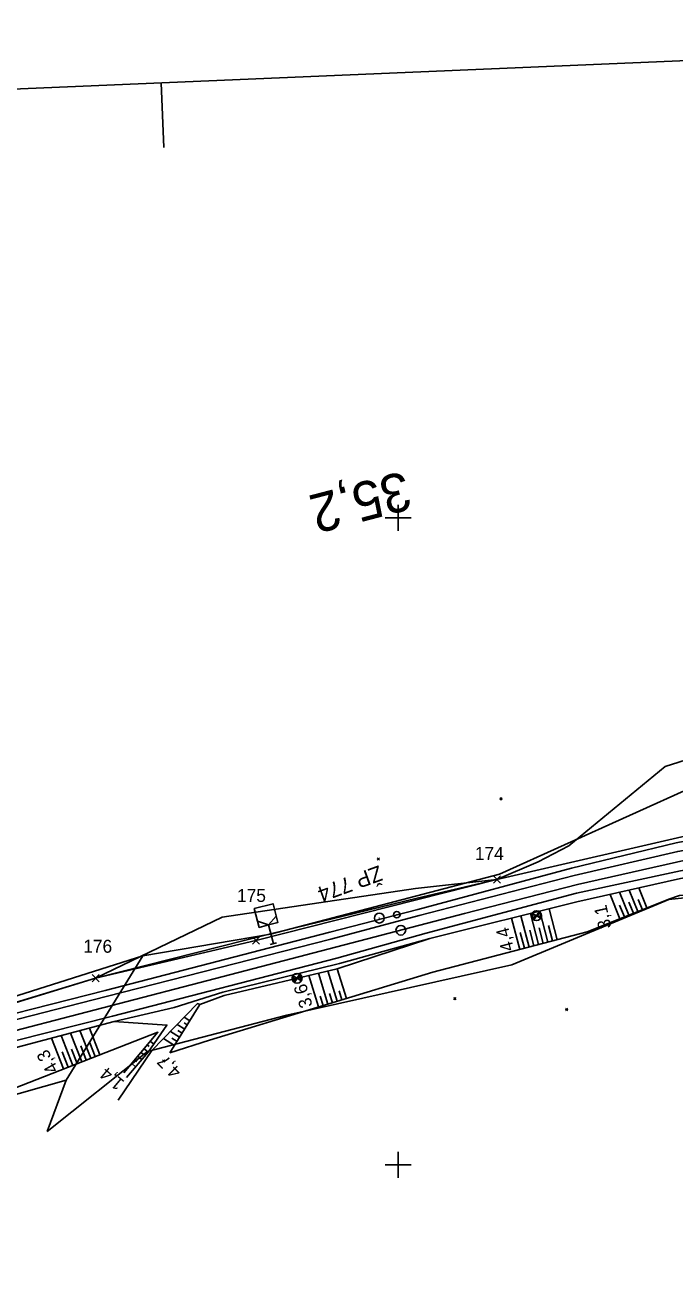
# Model space of a CAD drawing. Extents: x -806456 to -805395, y -1150847 to -1150506.
# Drawn here: x -806057.6 to -805957.2, y -1150719.3 to -1150523.9 of the extents above; entities that cross this region are included whole.
import ezdxf

# ---------------------------------------------------------------- set-up
doc = ezdxf.new("R2010")
doc.units = 0
for name, color, linetype in [('0381KM032-037P - Vrstva 1', 7, 'Continuous'), ('0381KM032-037P - Vrstva 4', 7, 'Continuous'), ('0381KM032-037P - Vrstva 48', 7, 'Continuous'), ('0381KM032-037P - Vrstva 49', 7, 'Continuous'), ('0381KM032-037P - Vrstva 55', 7, 'Continuous'), ('0381KM032-037P - Vrstva 7', 7, 'Continuous'), ('Default', 7, 'Continuous'), ('formát', 7, 'Continuous'), ('hran DP - hran DP', 7, 'Continuous'), ('krizky_1000 - Vrstva 1', 7, 'Continuous'), ('PSR_C2_2_Lomove_body_Vimperk - Vrstva 60', 7, 'Continuous'), ('PSR_C2_2_trasa_Vimperk - Kabelová trasa', 7, 'Continuous'), ('vyt_sit - stávající', 7, 'Continuous')]:
    doc.layers.add(name, color=color, linetype=linetype)

msp = doc.modelspace()

# ---------------------------------------------------------------- linework, layer by layer
at = {"layer": '0381KM032-037P - Vrstva 1'}
for points in [[(-805955.36, -1150652.84), (-805972.27, -1150656.66), (-805989.76, -1150661.17)], [(-805989.76, -1150661.17), (-806027.03, -1150670.9), (-806064.32, -1150680.56), (-806101.67, -1150690.24), (-806138.44, -1150699.75), (-806158.28, -1150704.94), (-806163.64, -1150706.34), (-806175.38, -1150709.4), (-806186.46, -1150712.29), (-806205.2, -1150717.19), (-806213.26, -1150719.29)]]:
    msp.add_lwpolyline(points, dxfattribs=at)
at = {"layer": '0381KM032-037P - Vrstva 4'}
for points in [[(-805920.59, -1150645.08), (-805938.49, -1150646.69), (-805957, -1150650.24), (-805973.18, -1150654.13), (-805996.94, -1150660.52), (-806010.57, -1150664.04), (-806045.29, -1150673.07), (-806070.44, -1150679.45), (-806076.44, -1150680.94), (-806080.95, -1150682.04), (-806094.16, -1150685.34), (-806107.83, -1150689.09)], [(-805923.83, -1150646.61), (-805939.39, -1150648.49), (-805956.78, -1150651.56), (-805972.77, -1150655.27), (-805996.74, -1150661.47), (-806010.38, -1150665.11), (-806045.15, -1150673.98), (-806070.28, -1150680.43), (-806094.02, -1150686.67), (-806107.78, -1150690.05)], [(-805923.37, -1150650.9), (-805938.15, -1150652.42), (-805956.35, -1150655.74), (-805972.37, -1150659.35), (-805995.12, -1150665.03), (-806009.04, -1150668.86), (-806027.1, -1150673.31), (-806034.62, -1150675.7), (-806043.91, -1150677.85), (-806068.97, -1150684.48)], [(-805923.42, -1150649.97), (-805938.4, -1150651.47), (-805956.35, -1150654.55), (-805972.44, -1150657.98), (-805995.68, -1150664.21)], [(-805995.68, -1150664.21), (-806009.49, -1150668.04), (-806044.17, -1150677), (-806069.3, -1150683.37)]]:
    msp.add_lwpolyline(points, dxfattribs=at)
at = {"layer": '0381KM032-037P - Vrstva 48'}
for p, q in [((-805962.94, -1150660.84), (-805964.27, -1150657.52)), ((-805961.55, -1150660.28), (-805962.79, -1150657.19)), ((-805965.72, -1150661.96), (-805967.24, -1150658.19)), ((-805964.33, -1150661.4), (-805965.76, -1150657.86)), ((-805963.64, -1150661.12), (-805964.33, -1150659.41)), ((-805962.24, -1150660.56), (-805962.89, -1150658.96)), ((-805978.31, -1150665.95), (-805979.56, -1150661.14)), ((-805976.86, -1150665.57), (-805978.1, -1150660.78)), ((-805975.4, -1150665.2), (-805976.65, -1150660.41)), ((-805965.03, -1150661.68), (-805965.76, -1150659.85)), ((-805981.21, -1150666.7), (-805982.47, -1150661.87)), ((-805979.76, -1150666.33), (-805981.01, -1150661.51)), ((-805977.58, -1150665.76), (-805978.21, -1150663.36)), ((-805976.13, -1150665.38), (-805976.75, -1150662.99)), ((-805980.48, -1150666.52), (-805981.11, -1150664.1)), ((-805979.03, -1150666.14), (-805979.66, -1150663.73)), ((-806012.31, -1150675.59), (-806013.79, -1150670.73)), ((-806010.87, -1150675.15), (-806012.33, -1150670.38)), ((-806009.44, -1150674.72), (-806010.87, -1150670.03)), ((-806008, -1150674.28), (-806009.41, -1150669.68)), ((-806008.72, -1150674.5), (-806009.14, -1150673.1)), ((-806011.59, -1150675.37), (-806012.03, -1150673.93)), ((-806010.15, -1150674.93), (-806010.59, -1150673.52)), ((-806046.12, -1150682.99), (-806047.73, -1150678.86)), ((-806032.99, -1150679.01), (-806034.14, -1150678.29)), ((-806032.59, -1150678.37), (-806033.1, -1150678.06)), ((-806032.2, -1150677.73), (-806033.07, -1150677.19)), ((-806051.71, -1150685.17), (-806053.56, -1150680.4)), ((-806050.31, -1150684.62), (-806052.1, -1150680.01)), ((-806048.91, -1150684.08), (-806050.65, -1150679.63)), ((-806047.52, -1150683.53), (-806049.19, -1150679.24)), ((-806038.31, -1150680.89), (-806037.77, -1150681.34)), ((-806034.58, -1150681.55), (-806036.29, -1150680.49)), ((-806033.78, -1150680.28), (-806035.21, -1150679.39)), ((-806034.18, -1150680.92), (-806034.96, -1150680.43)), ((-806033.39, -1150679.64), (-806034.03, -1150679.24)), ((-806051.01, -1150684.89), (-806051.92, -1150682.55)), ((-806049.61, -1150684.35), (-806050.49, -1150682.09)), ((-806048.21, -1150683.81), (-806049.07, -1150681.62)), ((-806046.82, -1150683.26), (-806047.64, -1150681.16)), ((-806039.75, -1150682.62), (-806039.43, -1150682.88)), ((-806039.27, -1150682.04), (-806038.62, -1150682.58)), ((-806038.79, -1150681.47), (-806038.49, -1150681.71)), ((-806041.19, -1150684.34), (-806040.59, -1150684.84)), ((-806040.71, -1150683.77), (-806040.41, -1150684.02)), ((-806040.23, -1150683.19), (-806039.61, -1150683.71))]:
    msp.add_line(p, q, dxfattribs=at)
at = {"layer": '0381KM032-037P - Vrstva 49'}
for p, q in [((-805984.28, -1150643.25), (-805983.92, -1150643.6)), ((-805983.92, -1150643.25), (-805984.27, -1150643.6)), ((-806002.88, -1150652.52), (-806003.24, -1150652.88)), ((-806003.24, -1150652.52), (-806002.88, -1150652.88)), ((-805991.06, -1150674.14), (-805991.41, -1150674.5)), ((-805991.41, -1150674.14), (-805991.06, -1150674.5)), ((-805973.79, -1150675.81), (-805974.14, -1150676.16)), ((-805974.14, -1150675.81), (-805973.79, -1150676.16)), ((-806036.06, -1150683.77), (-806036.41, -1150684.12)), ((-806036.41, -1150683.77), (-806036.06, -1150684.12))]:
    msp.add_line(p, q, dxfattribs=at)
for points in [[(-805973.62, -1150650.67), (-805958.72, -1150638.45), (-805944.76, -1150634.02), (-805913.4, -1150627.48)], [(-806076.44, -1150680.94), (-806070.44, -1150679.45), (-806045.29, -1150673.07), (-806010.57, -1150664.04), (-805996.94, -1150660.52), (-805973.18, -1150654.13), (-805957, -1150650.24), (-805938.49, -1150646.69)], [(-805973.62, -1150650.67), (-805978.37, -1150653.15), (-805984.72, -1150655.91), (-805997.34, -1150657.28), (-806027.21, -1150661.72), (-806046.76, -1150671.15)], [(-805923.37, -1150650.9), (-805938.15, -1150652.42), (-805956.35, -1150655.74), (-805972.37, -1150659.35), (-805995.12, -1150665.03)], [(-805923.15, -1150654.86), (-805936.98, -1150655.81), (-805944.5, -1150657.57), (-805956.52, -1150658.37), (-805958.13, -1150658.91), (-805970.8, -1150664), (-805994.63, -1150670.19)], [(-805984.72, -1150655.91), (-805997.04, -1150658.76), (-806019.75, -1150664.3), (-806046.76, -1150671.15)], [(-805995.12, -1150665.03), (-806009.04, -1150668.86), (-806027.1, -1150673.31), (-806034.62, -1150675.7), (-806043.91, -1150677.85), (-806068.97, -1150684.48)], [(-805995.12, -1150665.03), (-806009.41, -1150669.68), (-806026.88, -1150673.84), (-806030.63, -1150675.21), (-806035.27, -1150682.66)], [(-806046.76, -1150671.15), (-806070.76, -1150678.42)], [(-806035.27, -1150682.66), (-806029.14, -1150680.74), (-805994.63, -1150670.19)], [(-806043.26, -1150689.98), (-806038.08, -1150682.32), (-806030.99, -1150675.07), (-806030.63, -1150675.21)], [(-806042.01, -1150686.47), (-806038.62, -1150682.58), (-806035.75, -1150678.39), (-806043.91, -1150677.85)], [(-806042.38, -1150685.77), (-806037.14, -1150679.5), (-806067.5, -1150691.31), (-806072.52, -1150696.14), (-806083.69, -1150697.11)]]:
    msp.add_lwpolyline(points, dxfattribs=at)
at = {"layer": '0381KM032-037P - Vrstva 55'}
msp.add_line((-806039.45, -1150667.69), (-806051.33, -1150686.88), dxfattribs=at)
at = {"layer": '0381KM032-037P - Vrstva 7'}
for p, q in [((-806000.26, -1150661.33), (-806000.16, -1150661.33)), ((-806020.03, -1150662.91), (-806019.27, -1150665.81)), ((-806019.76, -1150665.94), (-806018.79, -1150665.69))]:
    msp.add_line(p, q, dxfattribs=at)
for points in [[(-806020.03, -1150662.91), (-806018.58, -1150662.53), (-806019.34, -1150659.63), (-806022.24, -1150660.39), (-806021.48, -1150663.29), (-806020.03, -1150662.91)], [(-806021.74, -1150662.32), (-806020.03, -1150662.91), (-806018.83, -1150661.56)]]:
    msp.add_lwpolyline(points, dxfattribs=at)
for centre, radius in [((-806000.21, -1150661.33), 0.5), ((-805999.58, -1150663.73), 0.75)]:
    msp.add_circle(centre, radius, dxfattribs=at)
at = {"layer": 'formát'}
for p, q in [((-805826.83, -1150523.88), (-806456.26, -1150550.6)), ((-806036.64, -1150532.78), (-806036.21, -1150542.77))]:
    msp.add_line(p, q, dxfattribs=at)
at = {"layer": 'hran DP - hran DP'}
for p, q in [((-805984.31, -1150655.05), (-805954.21, -1150641.47)), ((-806019.74, -1150664.32), (-805984.31, -1150655.05)), ((-805958.14, -1150658.97), (-805982.42, -1150669.1)), ((-805944.43, -1150657.58), (-805958.14, -1150658.97)), ((-806039.45, -1150667.69), (-806019.74, -1150664.32)), ((-806073.91, -1150678.57), (-806039.45, -1150667.69)), ((-805982.42, -1150669.1), (-806017.22, -1150676.88)), ((-806017.22, -1150676.88), (-806038.72, -1150682.46)), ((-806038.72, -1150682.46), (-806054.27, -1150694.84)), ((-806051.33, -1150686.88), (-806067.49, -1150691.49)), ((-806054.27, -1150694.84), (-806051.33, -1150686.88))]:
    msp.add_line(p, q, dxfattribs=at)
at = {"layer": 'krizky_1000 - Vrstva 1'}
for points in [[(-806000, -1150598), (-806000, -1150602)], [(-806002, -1150600), (-805998, -1150600)], [(-806000, -1150698), (-806000, -1150702)], [(-806002, -1150700), (-805998, -1150700)]]:
    msp.add_lwpolyline(points, dxfattribs=at)
at = {"layer": 'PSR_C2_2_Lomove_body_Vimperk - Vrstva 60'}
for p, q in [((-805985.27, -1150656.46), (-805984.17, -1150655.35)), ((-805984.17, -1150656.46), (-805985.27, -1150655.35)), ((-806022.53, -1150665.87), (-806021.43, -1150664.77)), ((-806021.43, -1150665.87), (-806022.53, -1150664.77)), ((-806047.31, -1150671.7), (-806046.21, -1150670.6)), ((-806046.21, -1150671.7), (-806047.31, -1150670.6))]:
    msp.add_line(p, q, dxfattribs=at)
at = {"layer": 'PSR_C2_2_trasa_Vimperk - Kabelová trasa'}
for p, q in [((-805984.72, -1150655.91), (-805945.75, -1150646.88)), ((-806021.98, -1150665.32), (-805984.72, -1150655.91))]:
    msp.add_line(p, q, dxfattribs=at)
msp.add_lwpolyline([(-806070.84, -1150678.49), (-806046.76, -1150671.15), (-806021.98, -1150665.32)], dxfattribs=at)
at = {"layer": 'vyt_sit - stávající'}
for p, q in [((-805979.05, -1150661.23), (-805979.34, -1150661.72)), ((-805979.28, -1150661.1), (-805978.61, -1150661.49)), ((-805978.79, -1150661.38), (-805979.17, -1150662.01)), ((-805978.61, -1150661.49), (-805978.22, -1150660.83)), ((-805978.07, -1150660.95), (-805978.44, -1150661.58)), ((-805977.89, -1150661.24), (-805978.19, -1150661.74)), ((-806002.97, -1150661.86), (-806002.87, -1150661.86)), ((-805978.61, -1150661.49), (-805979, -1150662.15)), ((-805977.96, -1150661.87), (-805978.61, -1150661.49)), ((-806016.06, -1150670.9), (-806016.35, -1150671.39)), ((-806016.29, -1150670.77), (-806015.62, -1150671.16)), ((-806015.8, -1150671.06), (-806016.17, -1150671.69)), ((-806015.62, -1150671.16), (-806016.01, -1150671.82)), ((-806015.62, -1150671.16), (-806015.24, -1150670.5)), ((-806014.97, -1150671.54), (-806015.62, -1150671.16)), ((-806015.08, -1150670.62), (-806015.45, -1150671.26)), ((-806014.9, -1150670.91), (-806015.2, -1150671.41))]:
    msp.add_line(p, q, dxfattribs=at)
for centre, radius in [((-806002.92, -1150661.86), 0.756), ((-805978.61, -1150661.49), 0.764), ((-806015.62, -1150671.16), 0.764)]:
    msp.add_circle(centre, radius, dxfattribs=at)
for centre, radius, start, end in [((-805978.61, -1150661.49), 0.765, 149.6712, 239.5647), ((-805978.61, -1150661.49), 0.764, 328.9824, 59.3004), ((-806015.62, -1150671.16), 0.765, 149.8433, 239.7368), ((-806015.62, -1150671.16), 0.764, 329.1545, 59.4725)]:
    msp.add_arc(centre, radius, start, end, dxfattribs=at)

# ---------------------------------------------------------------- texts
at = {"layer": '0381KM032-037P - Vrstva 48'}
for s, rotation, p in [('3,1', 102.684, (-805967.01, -1150663.31)), ('4,4', 104.5589, (-805982.06, -1150666.72)), ('3,6', 106.9987, (-806013.19, -1150675.4)), ('4,3', 119.1846, (-806052.44, -1150685.23)), ('4,7', 134.6698, (-806033.39, -1150685.47)), ('1,4', 140.1468, (-806042.18, -1150687.14))]:
    msp.add_text(s, height=2, rotation=rotation, dxfattribs=at).set_placement(p)
at = {"layer": '0381KM032-037P - Vrstva 7'}
msp.add_text('35,2', height=6, rotation=194.6315, dxfattribs=at).set_placement((-805999, -1150592.71))
at = {"layer": 'Default'}
for s, p in [('174', (-805988.14, -1150652.87)), ('175', (-806024.9, -1150659.36)), ('176', (-806048.67, -1150667.21))]:
    msp.add_text(s, height=2, dxfattribs=at).set_placement(p)
at = {"layer": 'vyt_sit - stávající'}
msp.add_text('ŽP 774', height=2.4, rotation=200, dxfattribs=at).set_placement((-806002.96, -1150653.66))

doc.saveas('drawing.dxf')
